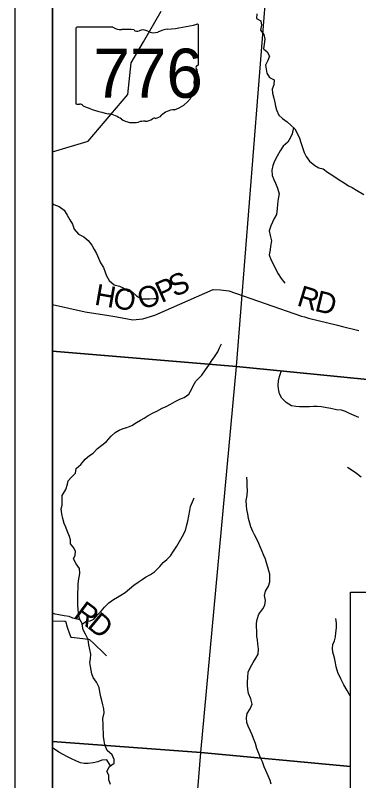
# Model space of a CAD drawing. Extents: x 0 to 34, y 0 to 22.
# Drawn here: x 23.417 to 24.339, y 16.062 to 18.118 of the extents above; entities that cross this region are included whole.
import ezdxf

# ---------------------------------------------------------------- set-up
doc = ezdxf.new("R2010")
doc.units = 0
for name, color, linetype in [('GM_X_Corporation', 7, 'Continuous'), ('GM_X_Minor_River', 7, 'Continuous'), ('GM_X_State_Location', 7, 'Continuous'), ('GM_X_State_Route', 7, 'Continuous'), ('GM_X_State_Shield', 7, 'Continuous'), ('GM_X_Township_Road', 7, 'Continuous'), ('GM_X_Township_Road_Text', 7, 'Continuous'), ('SH_Data', 7, 'Continuous')]:
    doc.layers.add(name, color=color, linetype=linetype)

msp = doc.modelspace()

# ---------------------------------------------------------------- linework, layer by layer
at = {"layer": 'GM_X_Corporation'}
for points in [[(26.1825, 18.4635), (26.1926, 18.5708), (26.207, 18.8068), (26.2271, 19.0168), (26.2277, 19.0233), (26.2281, 19.0286), (26.3029, 19.931), (25.7174, 19.9778), (25.482, 19.99), (25.2916, 20.0037), (25.117, 20.0172), (24.3889, 20.0736), (24.2296, 20.084), (23.8215, 20.1257), (23.5167, 20.1476), (23.5167, 14.1), (25.8273, 14.1), (25.8671, 14.5774), (25.9626, 15.7291)], [(25.0768, 17.6235), (25.0299, 17.0732), (24.0111, 17.1749), (24.0929, 18.2038), (24.656, 18.1575)], [(24.3169, 16.1005), (23.9154, 16.1379), (24.0111, 17.1749), (25.0299, 17.0732), (24.993, 16.5691)], [(24.9264, 15.7291), (24.8621, 15.0105), (23.8295, 15.0789), (23.9154, 16.1379), (24.3169, 16.1005)]]:
    msp.add_lwpolyline(points, dxfattribs=at)
for points in [[(23.5167, 18.2613), (23.5167, 17.2158), (24.0111, 17.1749), (24.0929, 18.2038)], [(23.5167, 17.2158), (23.5167, 16.1675), (23.9154, 16.1379), (24.0111, 17.1749)], [(23.5167, 16.1675), (23.5167, 15.1011), (23.8295, 15.0789), (23.9154, 16.1379)]]:
    msp.add_lwpolyline(points, close=True, dxfattribs=at)
at = {"layer": 'GM_X_Minor_River'}
for points in [[(24.0652, 18.1223), (24.0648, 18.1094), (24.0768, 18.1032), (24.0783, 18.0911), (24.0751, 18.0782), (24.0841, 18.0664), (24.0875, 18.0538), (24.0851, 18.0406), (24.0835, 18.0281), (24.0933, 18.0201), (24.0993, 18.0086), (24.0954, 17.9965), (24.0889, 17.9837)], [(24.0889, 17.9837), (24.0923, 17.9629), (24.0995, 17.9507), (24.1123, 17.9446), (24.1111, 17.9314), (24.1069, 17.9196), (24.108, 17.909), (24.1117, 17.8957), (24.1143, 17.884), (24.1154, 17.8741), (24.1181, 17.8642), (24.1248, 17.8498), (24.1346, 17.8411), (24.1474, 17.8315), (24.1576, 17.8224), (24.1674, 17.8129), (24.1731, 17.8034), (24.1806, 17.7882), (24.1836, 17.7768), (24.188, 17.7628), (24.1925, 17.7499), (24.1982, 17.7388), (24.2072, 17.7259), (24.2212, 17.7149), (24.2325, 17.7084), (24.2438, 17.7053), (24.2555, 17.6965), (24.2695, 17.6878), (24.2865, 17.6763), (24.3001, 17.6679), (24.3121, 17.6603), (24.3219, 17.6554), (24.3336, 17.6485), (24.3529, 17.637)], [(24.1639, 17.8163), (24.1602, 17.7996), (24.1564, 17.7898), (24.1488, 17.7773), (24.1366, 17.7664), (24.1279, 17.7539), (24.1199, 17.7395), (24.1134, 17.7263), (24.1088, 17.7149), (24.1057, 17.702), (24.1072, 17.688), (24.1109, 17.6774), (24.1154, 17.6668), (24.1211, 17.6538), (24.1255, 17.6387), (24.1232, 17.625), (24.1209, 17.611), (24.1201, 17.5985), (24.1182, 17.5833), (24.1124, 17.5724), (24.1079, 17.5625), (24.1033, 17.5523), (24.0991, 17.5387), (24.1017, 17.5262), (24.105, 17.5125), (24.1027, 17.4977), (24.1012, 17.4883), (24.0992, 17.4746), (24.1033, 17.4625), (24.1101, 17.4484), (24.1172, 17.4336), (24.1229, 17.4237), (24.1311, 17.4112), (24.1405, 17.3987)], [(23.5167, 17.6127), (23.5202, 17.6103), (23.5349, 17.6042), (23.5481, 17.5942), (23.5556, 17.5813), (23.5631, 17.5688), (23.5703, 17.5566), (23.5748, 17.5437), (23.5861, 17.5304), (23.6008, 17.5228), (23.6125, 17.5133), (23.6223, 17.5007), (23.6287, 17.4893), (23.6347, 17.4783), (23.6399, 17.4658), (23.6452, 17.4532), (23.6535, 17.4403), (23.6583, 17.4282), (23.6621, 17.4179), (23.6688, 17.4061), (23.682, 17.3943), (23.6964, 17.3905), (23.7062, 17.3863), (23.7198, 17.3775), (23.7304, 17.3756), (23.7424, 17.3642), (23.756, 17.3569), (23.7666, 17.3561), (23.7768, 17.3561), (23.7901, 17.3572), (23.7999, 17.3571)], [(23.5969, 16.4829), (23.5902, 16.4952), (23.5872, 16.5047), (23.5854, 16.5225), (23.5847, 16.5335), (23.5843, 16.5445), (23.5844, 16.568), (23.5852, 16.5782), (23.5856, 16.5892), (23.5868, 16.599), (23.5887, 16.6093), (23.5899, 16.6191), (23.5896, 16.632), (23.5801, 16.6446), (23.573, 16.6579), (23.5772, 16.6681), (23.5784, 16.6775), (23.5735, 16.6874), (23.5652, 16.6984), (23.5653, 16.7091), (23.5619, 16.7185), (23.5563, 16.7334), (23.5521, 16.7436), (23.548, 16.7531), (23.5447, 16.7664), (23.5421, 16.7789), (23.5395, 16.7926), (23.5429, 16.8024), (23.5429, 16.816), (23.5422, 16.8286), (23.5525, 16.8441), (23.5571, 16.8584), (23.5587, 16.8679), (23.5681, 16.8777), (23.5784, 16.8879), (23.5803, 16.9012), (23.5929, 16.9114), (23.6043, 16.9261), (23.6164, 16.9355), (23.6259, 16.9423), (23.6377, 16.9544), (23.649, 16.9635), (23.6619, 16.9737), (23.6741, 16.9873), (23.6847, 16.9974), (23.6953, 17.0039), (23.7067, 17.0084), (23.7166, 17.011), (23.7298, 17.0166), (23.7427, 17.0245), (23.7529, 17.0305), (23.7632, 17.0362), (23.7734, 17.043), (23.7871, 17.0505), (23.7969, 17.055), (23.8117, 17.0629), (23.8223, 17.0671), (23.8337, 17.0735), (23.8466, 17.081), (23.8606, 17.0878), (23.8708, 17.0911), (23.8833, 17.1009), (23.8902, 17.113), (23.8948, 17.1229), (23.9016, 17.135), (23.9176, 17.1516), (23.9275, 17.166), (23.9366, 17.1781), (23.945, 17.1909), (23.9522, 17.2007), (23.9606, 17.214), (23.9651, 17.225), (23.9705, 17.2355)], [(24.3393, 17.0374), (24.3269, 17.0435), (24.3144, 17.0489), (24.3042, 17.0535), (24.2929, 17.0573), (24.2793, 17.0585), (24.2641, 17.0623), (24.2536, 17.0639), (24.2396, 17.0662), (24.2275, 17.067), (24.2176, 17.0678), (24.207, 17.0663), (24.1942, 17.0664), (24.1806, 17.0664), (24.1707, 17.0672), (24.159, 17.0696), (24.1447, 17.0779), (24.1326, 17.0897), (24.1262, 17.1011), (24.1236, 17.1148), (24.1233, 17.1247), (24.1241, 17.1364), (24.1268, 17.1478), (24.1306, 17.161)], [(24.3459, 16.8774), (24.3335, 16.8873), (24.3195, 16.8969), (24.3093, 16.9037)], [(24.1038, 16.0531), (24.1016, 16.063), (24.0963, 16.0759), (24.0899, 16.0899), (24.0854, 16.0998), (24.0806, 16.1127), (24.0753, 16.1241), (24.0708, 16.1355), (24.0659, 16.1488), (24.0618, 16.1621), (24.057, 16.1754), (24.0532, 16.1852), (24.0487, 16.1951), (24.0427, 16.2088), (24.039, 16.2186), (24.0379, 16.2315), (24.0394, 16.2425), (24.0478, 16.255), (24.0531, 16.2679), (24.0498, 16.2827), (24.0434, 16.2963), (24.0412, 16.3085), (24.0408, 16.3183), (24.0405, 16.3278), (24.0413, 16.3395), (24.0425, 16.3536), (24.0482, 16.3672), (24.0558, 16.3801), (24.0631, 16.3918), (24.0688, 16.4024), (24.07, 16.4156), (24.0685, 16.43), (24.067, 16.4403), (24.0659, 16.4498), (24.0652, 16.4646), (24.0649, 16.4755), (24.0645, 16.4858), (24.0661, 16.4956), (24.0711, 16.5096), (24.0813, 16.524), (24.0867, 16.5342), (24.0886, 16.5467), (24.086, 16.5596), (24.0891, 16.571), (24.0967, 16.5846), (24.1005, 16.5967), (24.1009, 16.6062), (24.1002, 16.6168), (24.0976, 16.6263), (24.0954, 16.6362), (24.092, 16.6472), (24.0886, 16.6574), (24.0841, 16.6673), (24.08, 16.6775), (24.0755, 16.6889), (24.0706, 16.6995), (24.0665, 16.7094), (24.0594, 16.7223), (24.0549, 16.7318), (24.0496, 16.744), (24.0466, 16.7542), (24.0433, 16.7664), (24.041, 16.7793), (24.0388, 16.7906), (24.0377, 16.8013), (24.0374, 16.8145), (24.0393, 16.8285), (24.0401, 16.8422), (24.0398, 16.8536), (24.0395, 16.8657), (24.0388, 16.8778)], [(23.8798, 16.759), (23.8833, 16.7738), (23.8856, 16.7882), (23.8875, 16.7984), (23.8925, 16.8117), (23.8974, 16.8223)], [(23.6725, 16.0525), (23.668, 16.0646), (23.6681, 16.0771), (23.6628, 16.0874), (23.6697, 16.1003), (23.6826, 16.1097), (23.6819, 16.1192), (23.677, 16.1321), (23.6638, 16.1439), (23.6574, 16.1587), (23.6552, 16.1693), (23.6537, 16.1811), (23.6534, 16.1905), (23.6527, 16.2015), (23.6523, 16.2133), (23.652, 16.2292), (23.6551, 16.2444), (23.6547, 16.2557), (23.6518, 16.2664), (23.6488, 16.2774), (23.6469, 16.2872), (23.6439, 16.3013), (23.6417, 16.3126), (23.635, 16.3267), (23.6263, 16.34), (23.6226, 16.3495), (23.6203, 16.3593), (23.6185, 16.3688), (23.617, 16.3795), (23.6185, 16.3893), (23.6193, 16.4026), (23.6171, 16.4151), (23.6138, 16.4276), (23.6127, 16.442), (23.6055, 16.4557), (23.5992, 16.4678), (23.5966, 16.4826), (23.6061, 16.4902), (23.6174, 16.4913), (23.6276, 16.4958), (23.6383, 16.5086), (23.6478, 16.5181), (23.6565, 16.5287), (23.6679, 16.54), (23.6808, 16.5494), (23.691, 16.5551), (23.7005, 16.5603), (23.7123, 16.5679), (23.7237, 16.5773), (23.735, 16.5875), (23.7468, 16.5954), (23.7574, 16.6026), (23.7669, 16.6086), (23.7802, 16.6161), (23.7908, 16.6237), (23.8052, 16.6376), (23.8143, 16.6486), (23.8238, 16.6565), (23.8333, 16.6663), (23.8421, 16.6784), (23.8508, 16.6924), (23.858, 16.7045), (23.8653, 16.7174), (23.874, 16.734), (23.8779, 16.7492), (23.8798, 16.759)], [(23.5905, 16.4946), (23.5713, 16.4987), (23.5615, 16.5032), (23.5482, 16.5052), (23.5339, 16.5083), (23.524, 16.5098), (23.5167, 16.5119)], [(24.3169, 16.2902), (24.3139, 16.2949), (24.3083, 16.3048), (24.2996, 16.32), (24.291, 16.3356), (24.2835, 16.3527), (24.279, 16.3678), (24.2767, 16.3785), (24.2742, 16.3925), (24.27, 16.4077), (24.2686, 16.4172), (24.2701, 16.4285), (24.2739, 16.4384), (24.2766, 16.449), (24.2782, 16.4592), (24.2797, 16.4725), (24.2794, 16.4853), (24.2783, 16.4982)], [(23.6728, 16.1026), (23.6629, 16.1181), (23.6493, 16.1174), (23.6387, 16.1133), (23.6262, 16.1103), (23.6126, 16.1088), (23.602, 16.1085), (23.5922, 16.1108), (23.5789, 16.1158), (23.568, 16.1215), (23.557, 16.1268), (23.5457, 16.1326), (23.534, 16.1387), (23.5223, 16.1467), (23.5167, 16.1508)]]:
    msp.add_lwpolyline(points, dxfattribs=at)
at = {"layer": 'GM_X_State_Route'}
msp.add_lwpolyline([(23.5167, 17.7514), (23.6128, 17.7802), (23.7192, 17.9052), (23.7281, 17.9905), (23.7608, 18.0471), (23.8083, 18.1293)], dxfattribs=at)
at = {"layer": 'GM_X_State_Shield'}
for p, q in [((23.9087, 17.9862), (23.9087, 18.0909)), ((23.5791, 18.0825), (23.5791, 17.8824)), ((23.6789, 18.0859), (23.5823, 18.0859)), ((23.9086, 17.9862), (23.9087, 17.9862))]:
    msp.add_line(p, q, dxfattribs=at)
for centre, major_axis, start_param, end_param in [((23.7913, 18.3588), (0.3495, 0), 4.814394, 5.042369), ((23.905, 18.0913), (0.00367, 0), 6.141152, 7.989035), ((23.5829, 18.0829), (0.00382, 0), 1.712693, 3.28349), ((23.7018, 18.1092), (0.037, 0), 4.042523, 4.731795), ((23.7141, 17.9736), (0.133, 0), 1.404758, 1.657858), ((23.7443, 18.0839), (0.0107, 0), 3.836095, 5.185415), ((23.76, 18.0608), (0.0222, 0), 0.950623, 2.079405), ((23.7887, 18.0925), (0.0267, 0), 4.081561, 5.145723), ((23.8359, 18.0248), (0.0703, 0), 1.699011, 2.107814), ((23.9048, 17.9858), (0.00393, 0), 5.05454, 6.418171), ((23.9078, 17.9785), (0.00568, 0), 1.883978, 3.671073), ((23.8717, 17.9653), (0.0341, 0), 5.934695, 6.695948), ((23.9218, 17.9424), (0.0248, 0), 2.387724, 3.262537), ((23.8109, 17.9291), (0.0874, 0), 5.101752, 6.440018), ((23.5829, 17.8819), (0.00385, 0), 3.00124, 4.508301), ((23.5835, 17.9024), (0.0294, 0), 4.665946, 4.897461), ((23.5895, 17.8708), (0.0106, 0), 0.519207, 1.627899), ((23.7233, 18.0506), (0.2524, 0), 4.195997, 4.488961), ((23.8477, 17.8262), (0.0479, 0), 1.647645, 2.488434), ((23.6481, 17.7925), (0.079, 0), 0.823519, 1.323587), ((23.7871, 17.863), (0.0282, 0), 4.937069, 5.64225), ((23.7335, 17.8698), (0.0501, 0), 4.026481, 4.996735), ((23.7624, 17.8006), (0.0412, 0), 1.495662, 1.94098), ((23.7661, 17.8548), (0.0267, 0), 4.691044, 5.507374), ((23.7903, 17.8355), (0.00752, 0), 1.147584, 2.315152)]:
    msp.add_ellipse(centre, major_axis=major_axis, ratio=0.8, start_param=start_param, end_param=end_param, dxfattribs=at)
at = {"layer": 'GM_X_Township_Road'}
for points in [[(23.5167, 17.3413), (23.604, 17.3217), (23.668, 17.312), (23.6897, 17.3082), (23.7323, 17.2998), (23.7592, 17.3026), (23.792, 17.3123), (23.9479, 17.3816), (23.9681, 17.3806), (23.9903, 17.3777), (24.1856, 17.3101), (24.1934, 17.3078), (24.2048, 17.305), (24.282, 17.2859), (24.2955, 17.2826)], [(24.2955, 17.2826), (24.34, 17.2716)], [(23.5167, 16.4917), (23.5487, 16.4909), (23.5511, 16.4908), (23.5564, 16.475), (23.5625, 16.4569), (23.5656, 16.4479), (23.5751, 16.4467), (23.613, 16.4422), (23.616, 16.4418), (23.6276, 16.4306), (23.655, 16.404), (23.6619, 16.3974)]]:
    msp.add_lwpolyline(points, dxfattribs=at)
at = {"layer": 'SH_Data'}
for points in [[(23.4167, 21), (30.4167, 21), (30.4167, 14), (23.4167, 14)], [(23.5167, 20.9), (30.3167, 20.9), (30.3167, 14.1), (23.5167, 14.1)], [(24.3169, 16.5691), (26.1924, 16.5691), (26.1924, 15.7291), (24.3169, 15.7291)]]:
    msp.add_lwpolyline(points, close=True, dxfattribs=at)

# ---------------------------------------------------------------- texts
at = {"layer": 'GM_X_State_Location'}
for s in ['s', 'r']:
    msp.add_text(s, height=0.000189, dxfattribs=at).set_placement((23.7402, 17.9691))
msp.add_text('776', height=0.000189, rotation=0, dxfattribs=at).set_placement((23.6733, 17.9553))
at = {"layer": 'GM_X_State_Shield'}
msp.add_text('776', height=0.13184, dxfattribs=at).set_placement((23.6265, 17.8965))
at = {"layer": 'GM_X_Township_Road_Text'}
for s, rotation, p in [('P', 24.1545, (23.8094, 17.3447)), ('S', 23.9654, (23.8443, 17.3604)), ('H', 350.0454, (23.6272, 17.3412)), ('O', 18.3366, (23.756, 17.3267)), ('R', 343.0129, (24.1705, 17.3393)), ('O', 350.7057, (23.6771, 17.3325)), ('D', 346.3599, (24.2186, 17.3247)), ('R', 323.4759, (23.5702, 16.5028)), ('D', 320.4458, (23.6071, 16.4755))]:
    msp.add_text(s, height=0.0568, rotation=rotation, dxfattribs=at).set_placement(p)

doc.saveas('drawing.dxf')
